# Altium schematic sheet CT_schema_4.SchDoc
size 522 x 483 mm
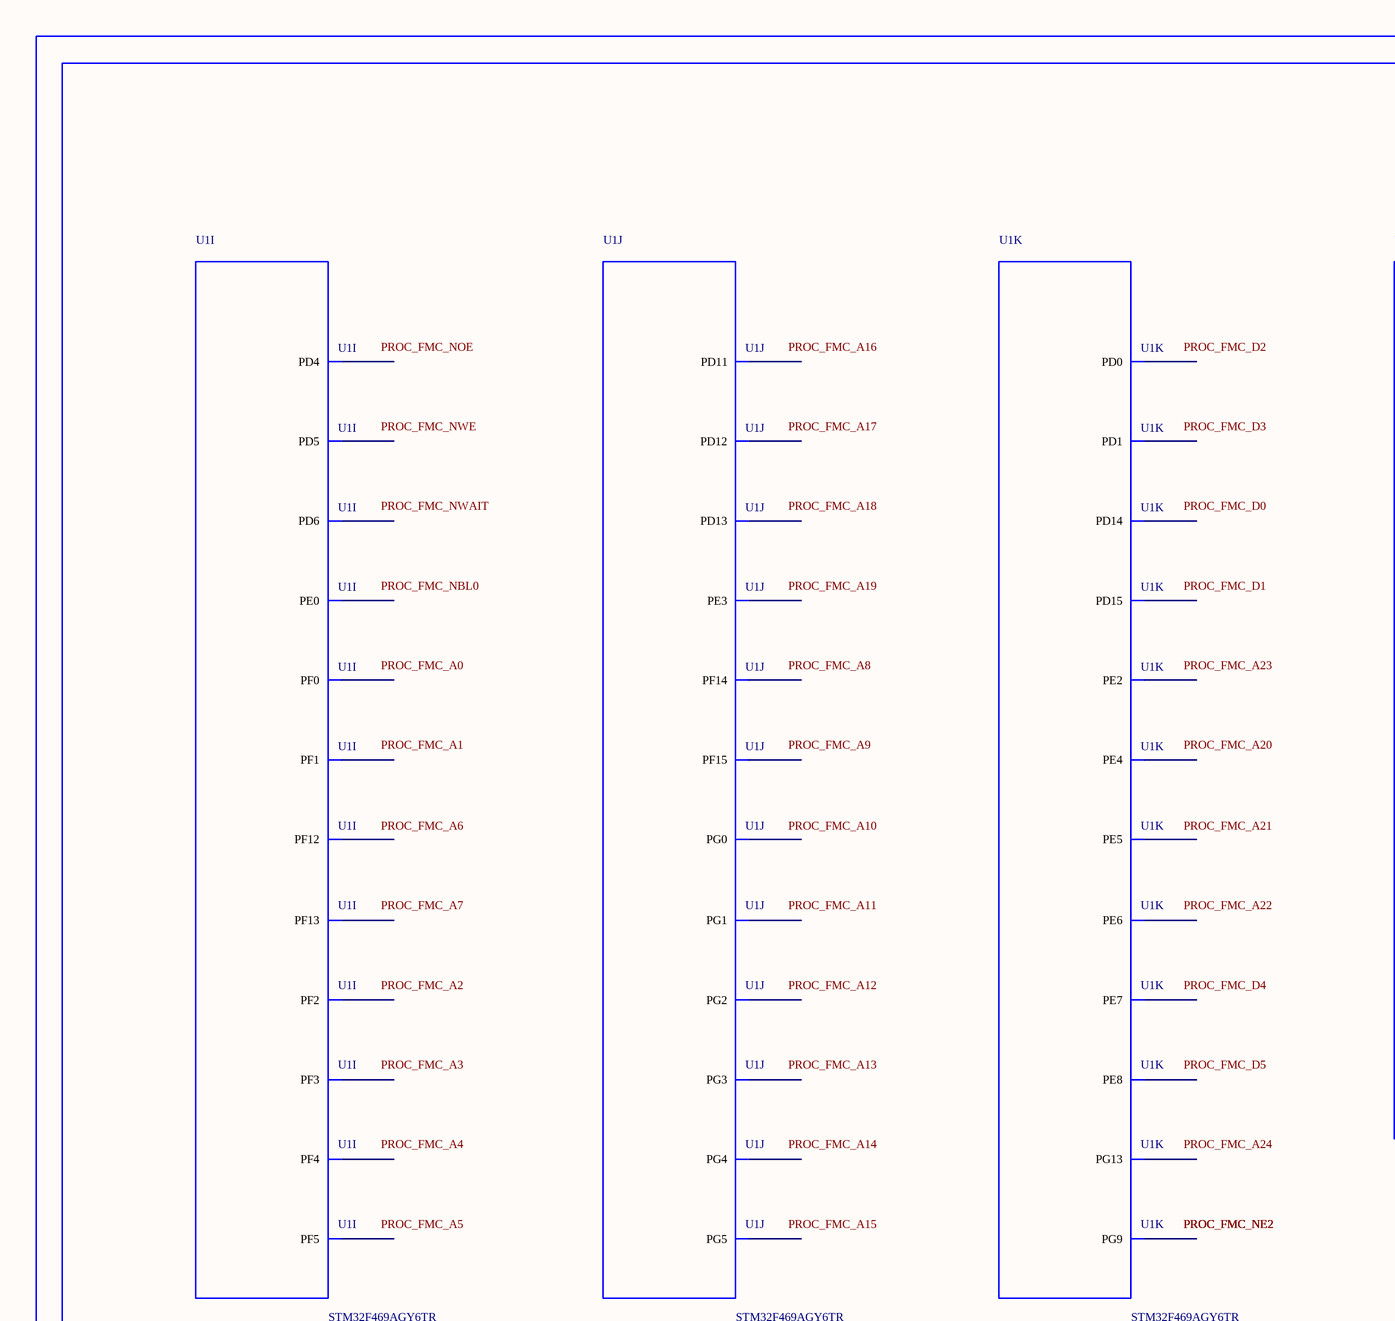
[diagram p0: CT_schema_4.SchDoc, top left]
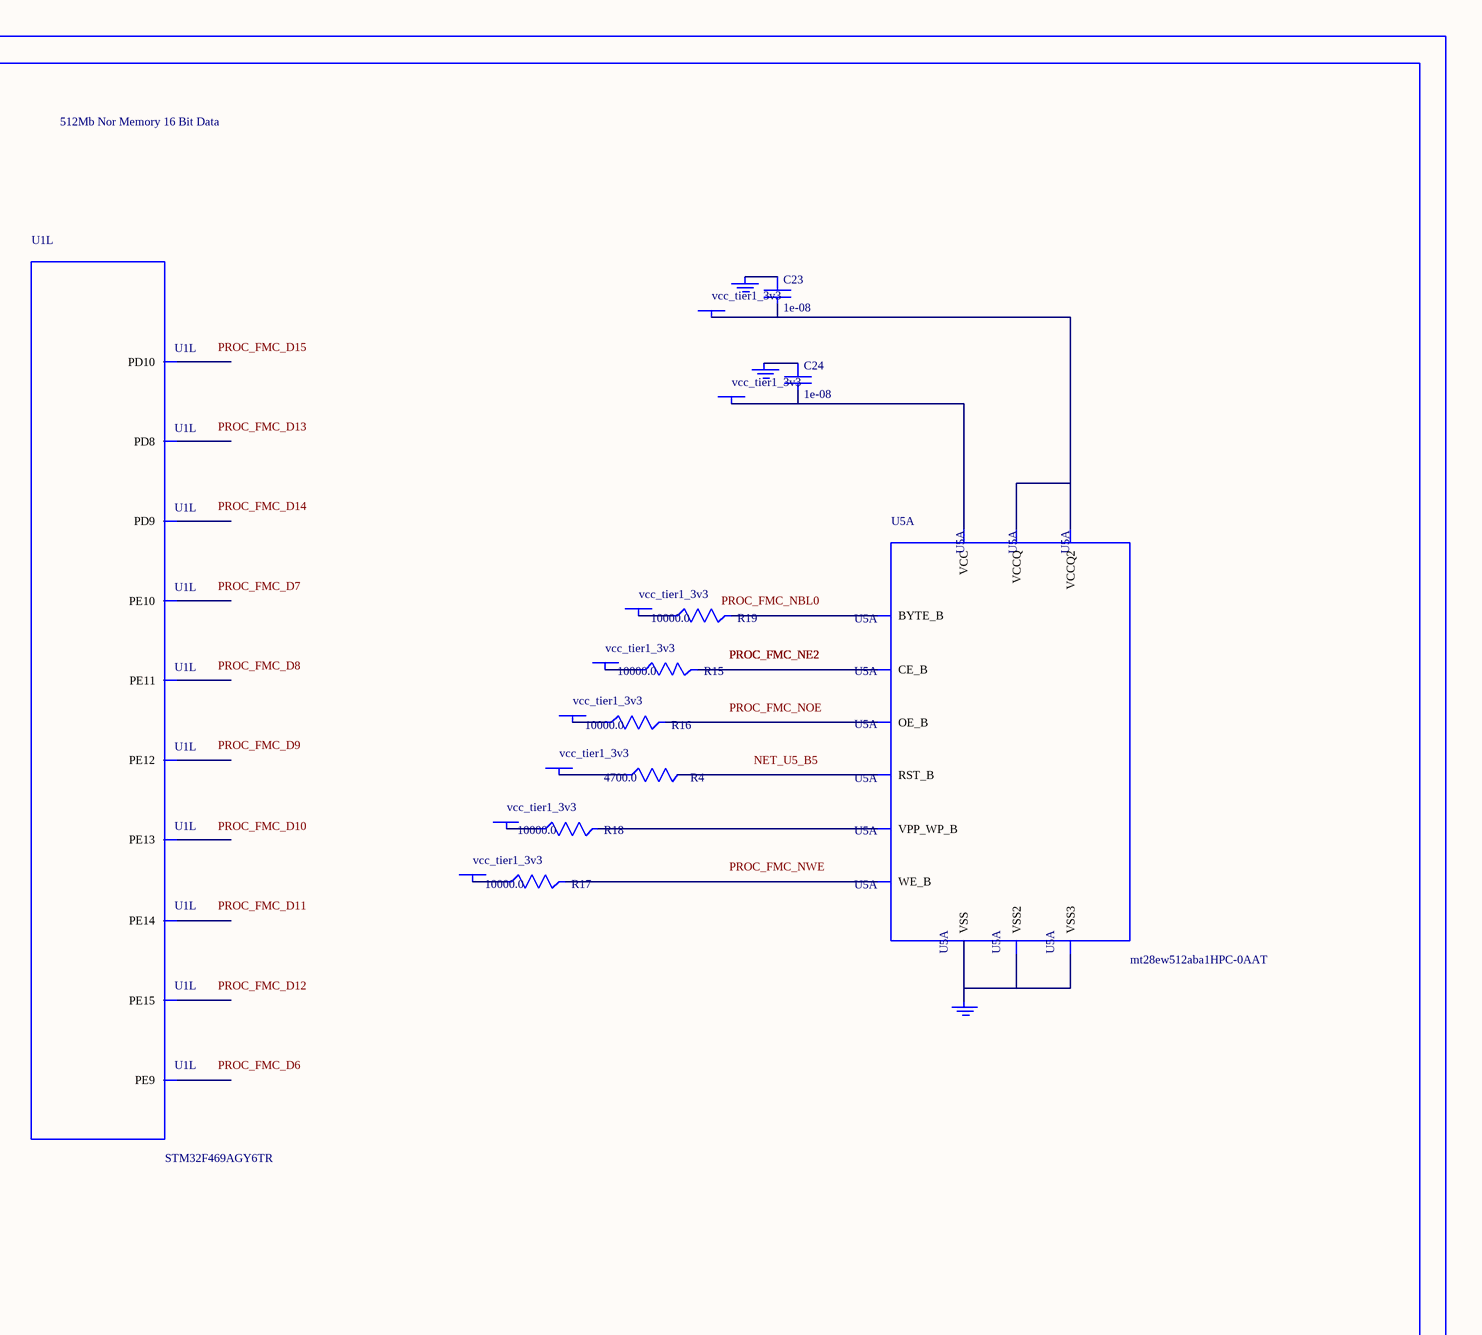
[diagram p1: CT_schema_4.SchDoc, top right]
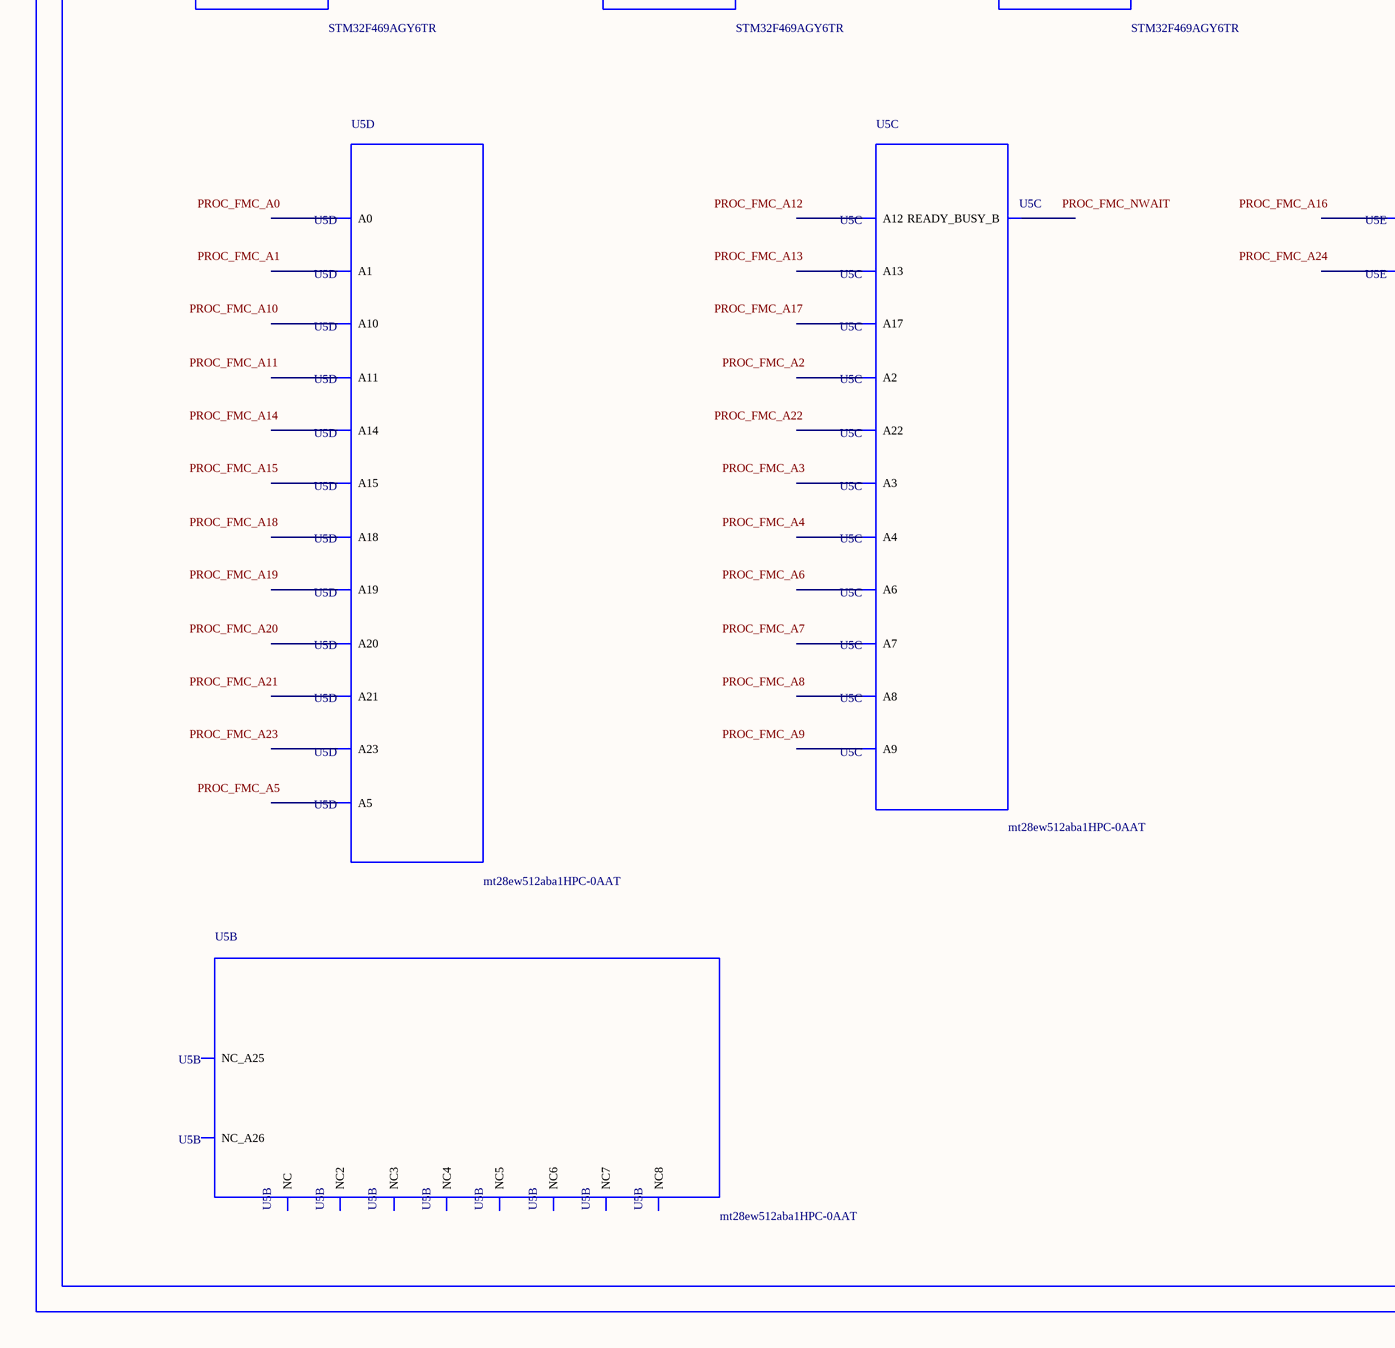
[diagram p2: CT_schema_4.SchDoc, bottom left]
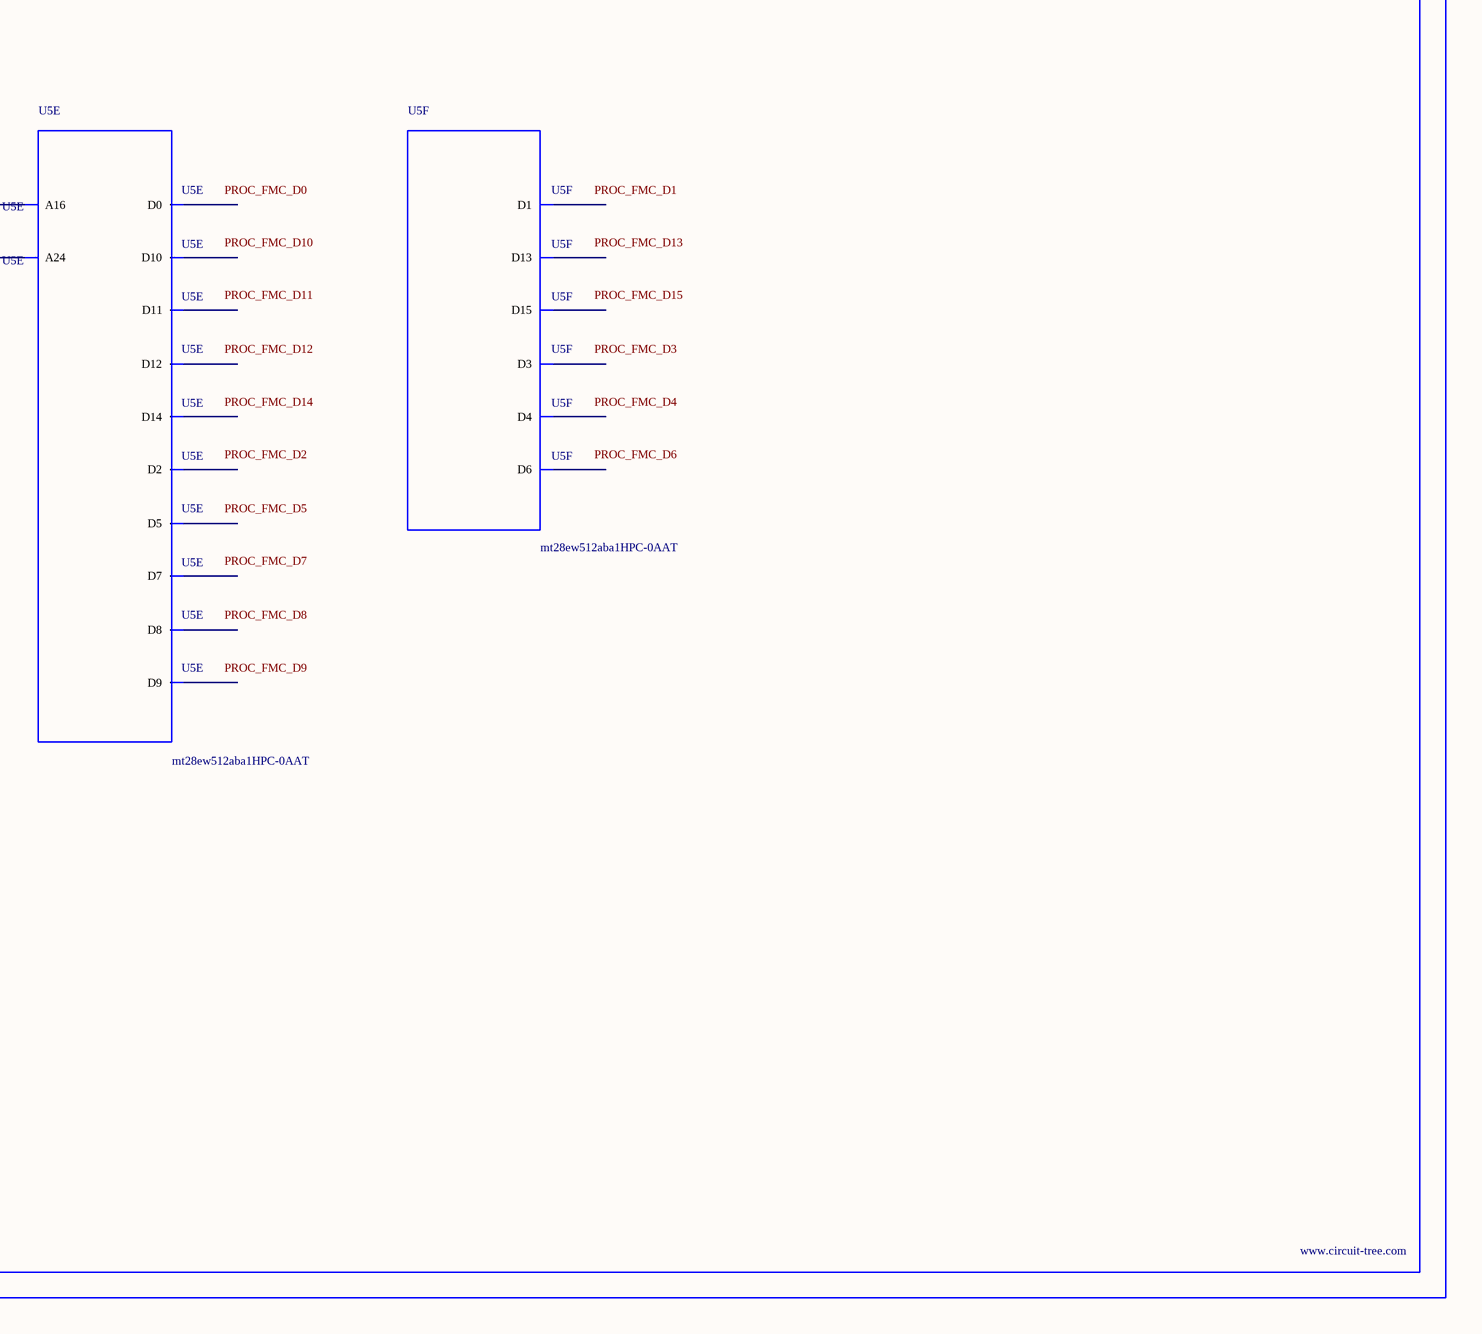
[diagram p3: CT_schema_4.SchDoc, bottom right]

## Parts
BORDER3  (no value)
C23  1e-08  [C0402]
C24  1e-08  [C0402]
GND_INSTANCE_3_0  (no value)
GND_INSTANCE_3_1  (no value)
GND_INSTANCE_3_2  (no value)
POWER_INSTANCE_3_0  vcc_tier1_3v3
POWER_INSTANCE_3_1  vcc_tier1_3v3
POWER_INSTANCE_3_2  vcc_tier1_3v3
POWER_INSTANCE_3_3  vcc_tier1_3v3
POWER_INSTANCE_3_4  vcc_tier1_3v3
POWER_INSTANCE_3_5  vcc_tier1_3v3
POWER_INSTANCE_3_6  vcc_tier1_3v3
POWER_INSTANCE_3_7  vcc_tier1_3v3
R4  4700.0  [R0603]
R15  10000.0  [R0603]
R16  10000.0  [R0603]
R17  10000.0  [R0603]
R18  10000.0  [R0603]
R19  10000.0  [R0603]
U1  STM32F469AGY6TR  [WLCSP168]  (parts I,J,K,L of 13)
U5  mt28ew512aba1HPC-0AAT  [LBGA-64]  (parts A,B,C,D,E,F of 6)

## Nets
NetC23_1: C23.1 GND_INSTANCE_3_0.0(GND)
NetC23_2: C23.2 POWER_INSTANCE_3_0.0(PWR) U5.D8(VCCQ) U5.F1(VCCQ2)
NetC24_1: C24.1 GND_INSTANCE_3_1.0(GND)
NetC24_2: C24.2 POWER_INSTANCE_3_1.0(PWR) U5.G5(VCC)
NetGND_INSTANCE_3_2_0: GND_INSTANCE_3_2.0(GND) U5.E8(VSS) U5.H2(VSS2) U5.H7(VSS3)
NetPOWER_INSTANCE_3_2_0: POWER_INSTANCE_3_2.0(PWR) R15.1
NetPOWER_INSTANCE_3_3_0: POWER_INSTANCE_3_3.0(PWR) R16.1
NetPOWER_INSTANCE_3_4_0: POWER_INSTANCE_3_4.0(PWR) R17.1
NetPOWER_INSTANCE_3_5_0: POWER_INSTANCE_3_5.0(PWR) R18.1
NetPOWER_INSTANCE_3_6_0: POWER_INSTANCE_3_6.0(PWR) R19.1
NetPOWER_INSTANCE_3_7_0: POWER_INSTANCE_3_7.0(PWR) R4.1
NetR4_2: R4.2 U5.B5(RST_B)
NetR15_2: R15.2 U5.F2(CE_B)
NetR16_2: R16.2 U5.G2(OE_B)
NetR17_2: R17.2 U5.A5(WE_B)
NetR18_2: R18.2 U5.B4(VPP_WP_B)
NetR19_2: R19.2 U5.F7(BYTE_B)

Not connected (* = marked no-connect by the designer): U1 A3(PD1) A10(PE0) B4(PD4) B12(PE5) C6(PD5) C11(PE4) D7(PG9) D11(PE6) E6(PD0) E7(PD6) E8(PG13) E10(PE3) F9(PE2) G1(PG5) G2(PG4) G4(PG3) G5(PG2) G10(PF0) G12(PF2) H4(PD13) H8(PF15) H10(PF1) H11(PF3) H12(PF5) J4(PD11) J5(PE14) J6(PG0) J7(PF13) J10(PF4) K6(PE9) L2(PD15) L3(PD14) L4(PD8) L6(PE13) L7(PF14) M2(PD12) M3(PD10) M6(PE12) M7(PE8) M8(PF12) N1(PD9) N6(PE11) N7(PE7) P5(PE15) P6(PE10) P7(PG1); U5 A1(NC) A2(A3) A3(A7) A4(READY_BUSY_B) A6(A9) A7(A13) A8(NC2) B1(NC_A26) B2(A4) B3(A17) B6(A8) B7(A12) B8(A22) C1(NC3) C2(A2) C3(A6) C4(A18) C5(A21) C6(A10) C7(A14) C8(A23) D1(NC4) D2(A1) D3(A5) D4(A20) D5(A19) D6(A11) D7(A15) E1(NC5) E2(A0) E3(D0) E4(D2) E5(D5) E6(D7) E7(A16) F3(D8) F4(D10) F5(D12) F6(D14) F8(A24) G1(NC6) G3(D9) G4(D11) G6(D13) G7(D15) G8(NC_A25) H1(NC7) H3(D1) H4(D3) H5(D4) H6(D6) H8(NC8)

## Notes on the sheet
- Labels drawn without touching a wire or pin: NET_U5_B5, PROC_FMC_A0, PROC_FMC_A1, PROC_FMC_A2, PROC_FMC_A3, PROC_FMC_A4, PROC_FMC_A5, PROC_FMC_A6, PROC_FMC_A7, PROC_FMC_A8, PROC_FMC_A9, PROC_FMC_A10, PROC_FMC_A11, PROC_FMC_A12, PROC_FMC_A13, PROC_FMC_A14, PROC_FMC_A15, PROC_FMC_A16, PROC_FMC_A17, PROC_FMC_A18, PROC_FMC_A19, PROC_FMC_A20, PROC_FMC_A21, PROC_FMC_A22, PROC_FMC_A23, PROC_FMC_A24, PROC_FMC_D0, PROC_FMC_D1, PROC_FMC_D2, PROC_FMC_D3, PROC_FMC_D4, PROC_FMC_D5, PROC_FMC_D6, PROC_FMC_D7, PROC_FMC_D8, PROC_FMC_D9, PROC_FMC_D10, PROC_FMC_D11, PROC_FMC_D12, PROC_FMC_D13, PROC_FMC_D14, PROC_FMC_D15, PROC_FMC_NBL0, PROC_FMC_NOE, PROC_FMC_NWAIT, PROC_FMC_NWE

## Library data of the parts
BORDER3 = BORDER_PAGE3
C23 C24 = C0402C103K3RAC
GND_INSTANCE_3_0-GND_INSTANCE_3_2 = GND
POWER_INSTANCE_3_0-POWER_INSTANCE_3_7 = PWR
R4 = RC0603JR-074K7L
R15-R19 = RC0603JR-0710KL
